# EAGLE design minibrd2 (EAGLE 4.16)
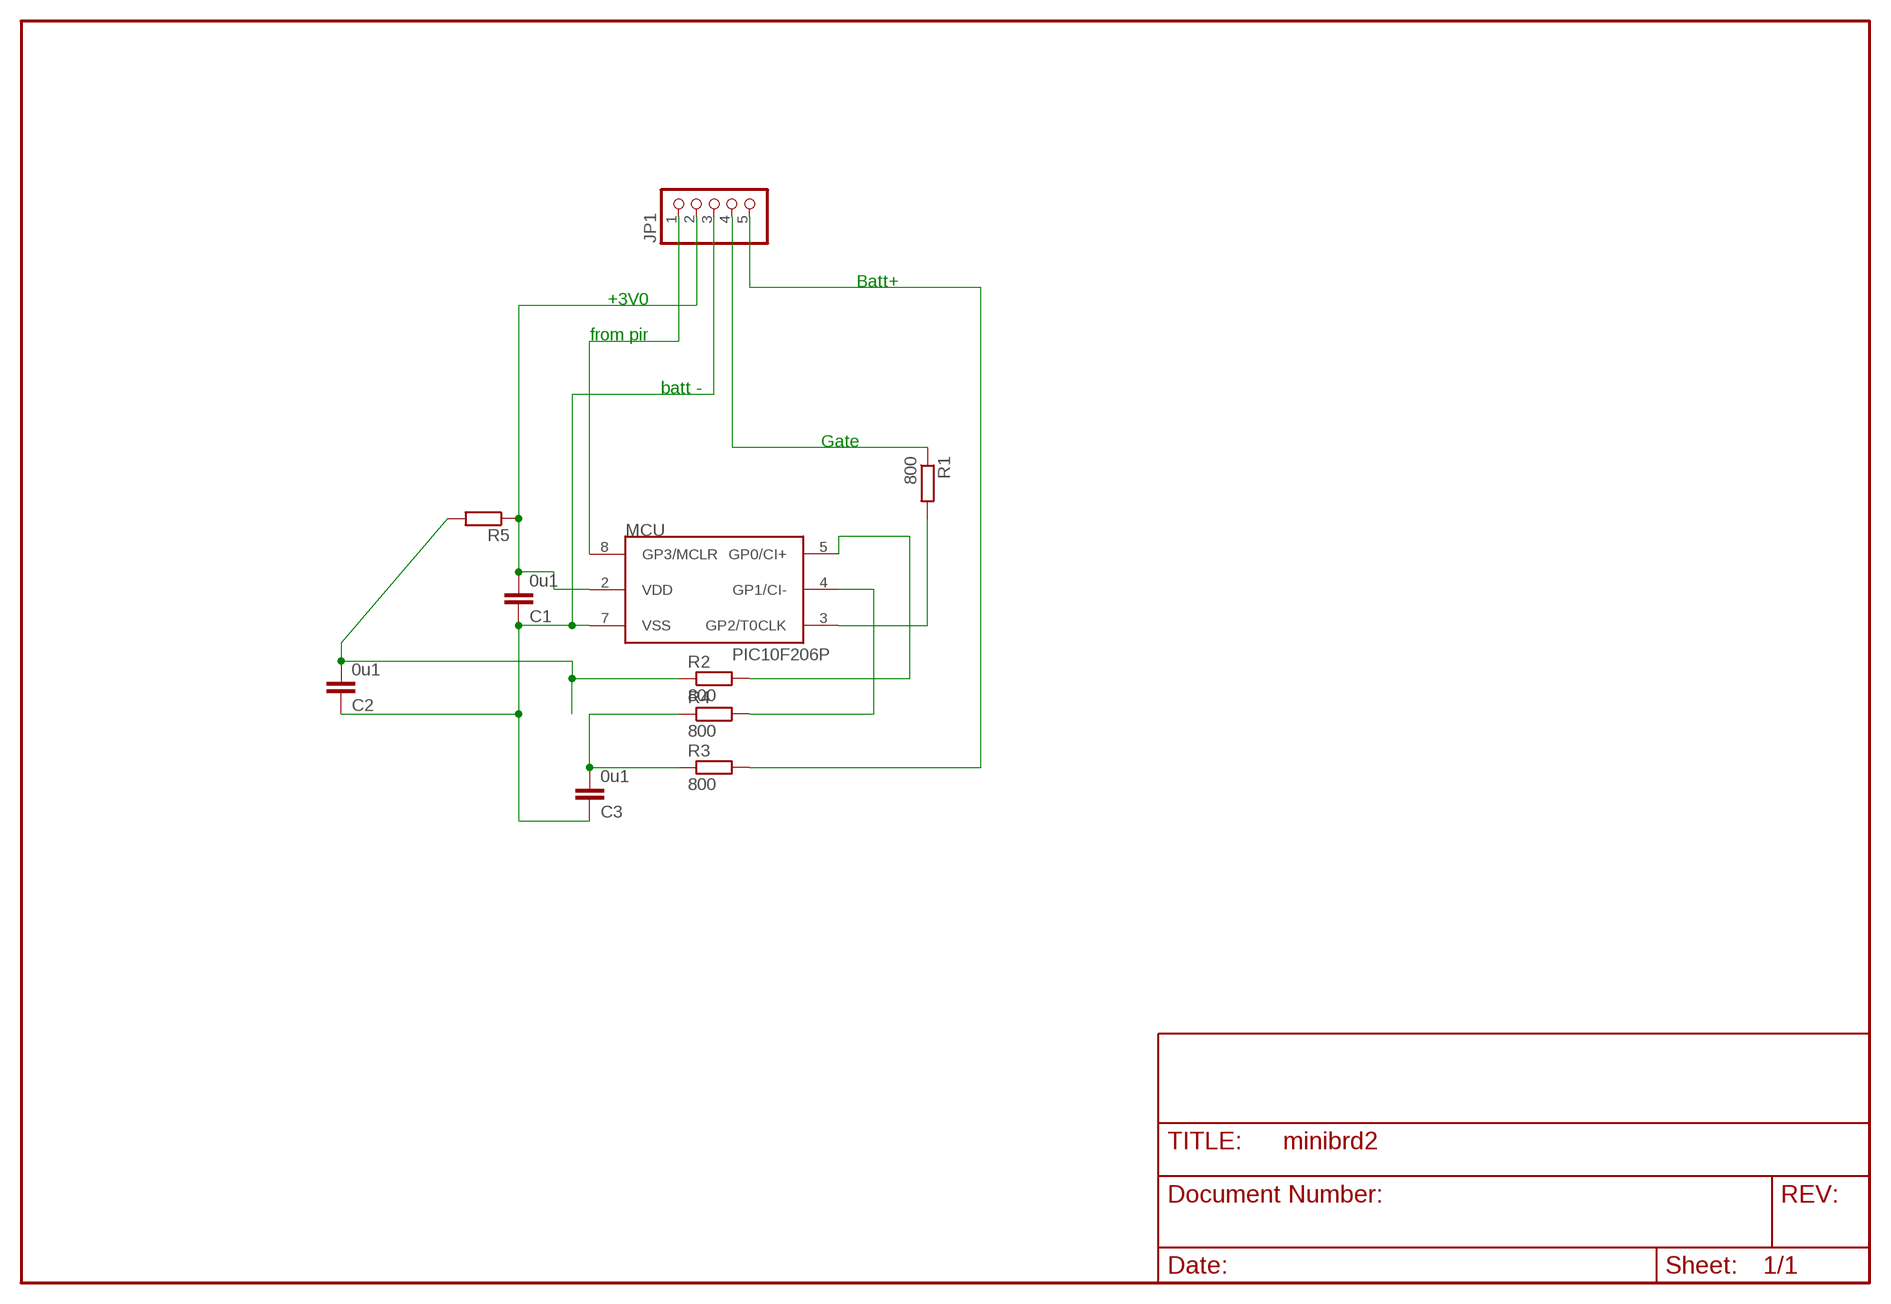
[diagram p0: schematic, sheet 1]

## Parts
C1  0u1  C-EUC1206  [C1206]
C2  0u1  C-EUC1206  [C1206]
C3  0u1  C-EUC1206  [C1206]
JP1  PINHD-1X5  [1X05]
MCU  PIC10F206P  [DIL8]
R1  800  R-EU_R1206  [R1206]
R2  800  R-EU_R1206  [R1206]
R3  800  R-EU_R1206  [R1206]
R4  800  R-EU_R1206  [R1206]
R5  R-EU_0613/5V  [P0613V]

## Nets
GATE: JP1.4 R1.1
N$1: C2.2 R2.1 R5.2
N$4: MCU.5(GP0/CI+) R2.2
N$5: MCU.3(GP2/T0CLK) R1.2
N$7: C3.2 R3.1 R4.1
N$8: MCU.4(GP1/CI-) R4.2
PIR: JP1.1 MCU.8(GP3/MCLR)
V3: C1.2 JP1.2 MCU.2(VDD) R5.1
V+: JP1.5 R3.2
V-: C1.1 C2.1 C3.1 JP1.3 MCU.7(VSS)

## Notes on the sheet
- Batt+
- +3V0
- from pir
- batt -
- Gate

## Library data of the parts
C1-C3 = rcl:C-EU: CAPACITOR, European symbol
JP1 = pinhead:PINHD-1X5: PIN HEADER
MCU = microchip-3:PIC10F2*: uPC nW 0,25/0,5k Program Flash memory Comparator
R1-R5 = rcl:R-EU_: RESISTOR, European symbol

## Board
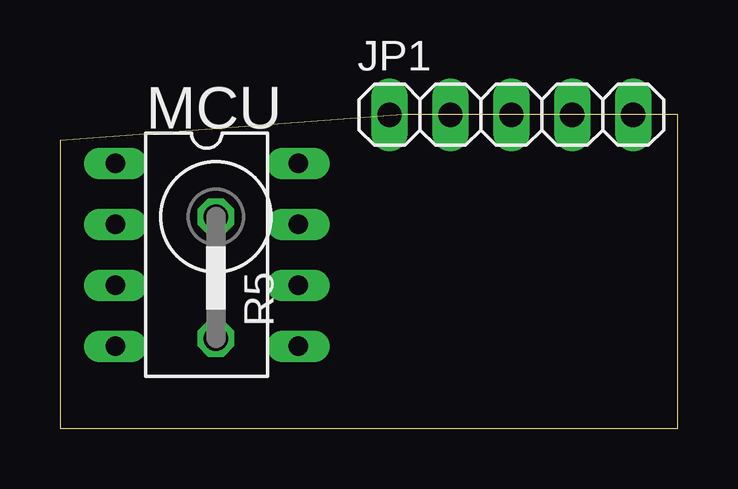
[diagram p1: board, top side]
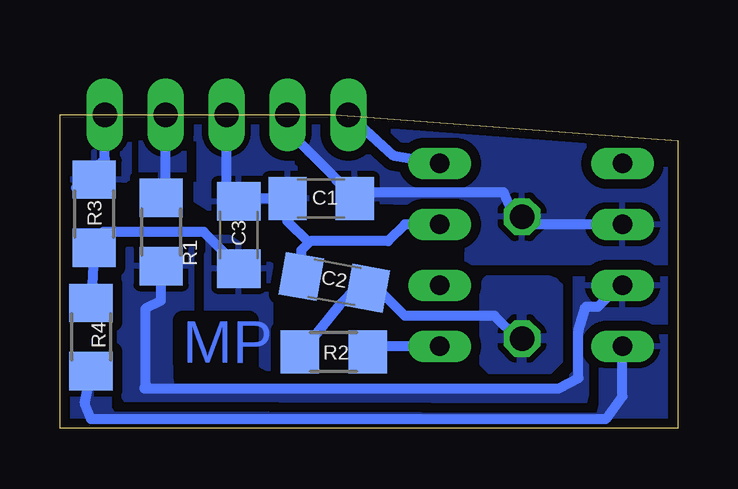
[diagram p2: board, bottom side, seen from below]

Size 25.77 x 13.08 mm. Coordinates in mm from the lower left corner, seen from the top.
Outline: 0,0 25.77,0 25.77,13.07 18,13.07 14.31,13.08 0,11.99 0,0
Copper layers (1*16): Top 0.035mm / dielectric 1.5mm / Bottom 0.035mm
Design rules "default": minimum track width 10mil, minimum drill 24mil, track to track 8mil, track to pad 8mil, pad to pad 8mil, via to via 8mil, smd to smd 8mil, copper to edge 1mil, drill to drill 8mil, minimum pad ring 10mil, minimum via ring 8mil, stop-mask expansion 4mil, vias tented up to drill 0mil, thermal gap 10mil

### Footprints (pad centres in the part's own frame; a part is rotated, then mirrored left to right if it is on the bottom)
C1206 = smd 1.6 x 1.8: 1 -1.4,0; 2 1.4,0
1X05 = drill 1.016 long: 1 -5.08,0; 2 -2.54,0; 3 0,0; 4 2.54,0; 5 5.08,0
DIL8 = drill 0.813 long: 1 -3.81,-3.81; 2 -1.27,-3.81; 3 1.27,-3.81; 4 3.81,-3.81; 5 3.81,3.81; 6 1.27,3.81; 7 -1.27,3.81; 8 -3.81,3.81
R1206 = smd 1.6 x 1.803: 1 -1.422,0; 2 1.422,0
P0613V = drill 1.016 octagon: 1 -2.54,0; 2 2.54,0

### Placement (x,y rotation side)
C1  14.88,9.58 0 bottom
C2  14.32,6.09 350 bottom
C3  18.31,8.06 270 bottom
JP1  18.82,13.08 0 top
MCU  6.12,7.23 270 top
R1  21.55,8.19 270 bottom
R2  14.35,3.18 0 bottom
R3  24.35,8.95 90 bottom
R4  24.47,3.81 270 bottom
R5  6.5,6.28 270 top

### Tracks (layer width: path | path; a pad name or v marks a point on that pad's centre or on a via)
GATE
  Bottom 0.406: 21.59,9.61 21.74,9.46 | 21.59,9.61 R1.1 21.55,9.77 21.36,9.96 JP1.4 | 21.59,9.61 21.36,9.84
  pour Bottom (isolate 0.406): 20.6,13.08 22.12,13.08 22.38,12.82 22.38,10.47 22.44,10.41 20.92,10.41 20.6,10.66
N$1
  Bottom 0.406: R5.2 6.69,3.74 7.65,4.69 11.39,4.69 12.86,6.16 C2.2 13.42,5.84 14.12,5.14 15.7,3.18 R2.1
  pour Bottom (isolate 0.406): 5.36,6.15 7.96,6.15 8.09,5.9 8.09,2.73 7.71,2.34 5.49,2.34 4.98,2.85 4.98,5.9 5.17,6.09
N$4
  Bottom 0.406: 13.03,3.31 13.04,3.3 | 13.03,3.31 R2.2 | MCU.5 12.92,3.42 13.03,3.31
N$5
  Bottom 0.406: R1.2 21.55,5.33 22.19,5.01 22.19,1.84 22.25,1.65 4.98,1.65 4.15,2.09 4.15,4.06 3.84,5.08 3.33,5.08 2.44,5.96 MCU.3
  pour Bottom (isolate 0.406, rank 2): 0.22,6.22 0.22,4.44 2.76,4.44 3.84,3.36 3.84,1.39 3.9,1.14 23.01,1.2 23.27,1.52 23.27,6.98 22.76,7.68 20.16,7.68 20.03,7.55 20.03,5.2 21.17,4.06 21.17,2.09 21.11,1.77 10.06,1.65 5.42,1.65 4.41,2.03 4.41,6.22
N$7
  Bottom 0.406: C3.2 18.31,6.73 19.77,8.19 23.96,8.19 24.62,7.53 R3.1 R4.1
  pour Bottom (isolate 0.406): 18.69,7.93 19.58,7.93 19.58,7.23 19.65,7.23 19.65,3.93 16.98,2.41 16.98,6.79
N$8
  Bottom 0.406: R4.2 24.73,1.01 24.47,0.38 3.01,0.38 2.31,1.33 2.31,3.23 2.44,3.36 2.37,3.42 MCU.4
  pour Bottom (isolate 0.406, rank 3): 0.22,3.81 0.22,0.31 0.41,0.12 24.98,0.12 25.36,0.5 25.36,2.15 25.11,2.41 23.9,2.41 23.46,1.96 23.46,1.46 23.2,1.2 3.71,1.2 3.65,1.27 3.65,3.23 3.65,3.42 3.26,3.81
PIR
  Bottom 0.406: MCU.8 10,11.04 11.84,11.36 JP1.1
V3
  Bottom 0.406: JP1.2 16.28,12.44 14.25,10.41 14.25,10.35 C1.2 | C1.2 | R5.1 6.57,8.88 | MCU.2 6.19,8.5 R5.1 | R5.1 6.82,8.82 7.26,9.84 13.23,9.84 13.56,9.58 | 13.56,9.58 13.61,9.52 | 13.56,9.58 C1.2
  pour Bottom (isolate 0.406): 0.34,11.68 0.34,8.57 0.28,6.92 8.79,6.92 8.72,9.39 13.42,9.46 13.93,9.39 14.31,10.6 16.79,12.5 16.79,12.63 16.6,12.82
V+
  Bottom 0.406: 24.03,11.11 25.11,10.03 25.04,10.03 24.73,10.35 R3.2 | 24.03,11.11 23.9,11.23 | 24.03,11.11 23.96,11.04 23.9,11.11 JP1.5
  pour Bottom (isolate 0.406): 22.89,12.82 25.17,12.76 25.68,12.63 25.68,10.35 25.55,10.09 23.46,10.09 22.89,10.47
V-
  Bottom 0.406: JP1.3 18.82,9.84 18.31,9.33 C3.1 18.19,9.58 18.18,9.58 C1.1 16.28,8.63 15.39,7.74 | MCU.7 11.39,8.5 12.09,7.81 15.33,7.81 15.39,7.74 | 15.39,7.74 15.71,7.42 15.71,7.11 15.58,6.98 15.64,6.92 C2.1
  pour Bottom (isolate 0.406, rank 2): 17.42,13.33 19.96,13.33 20.09,13.2 20.09,9.52 19.2,8.95 15.46,8.95 15.52,10.85

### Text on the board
Bottom: MP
